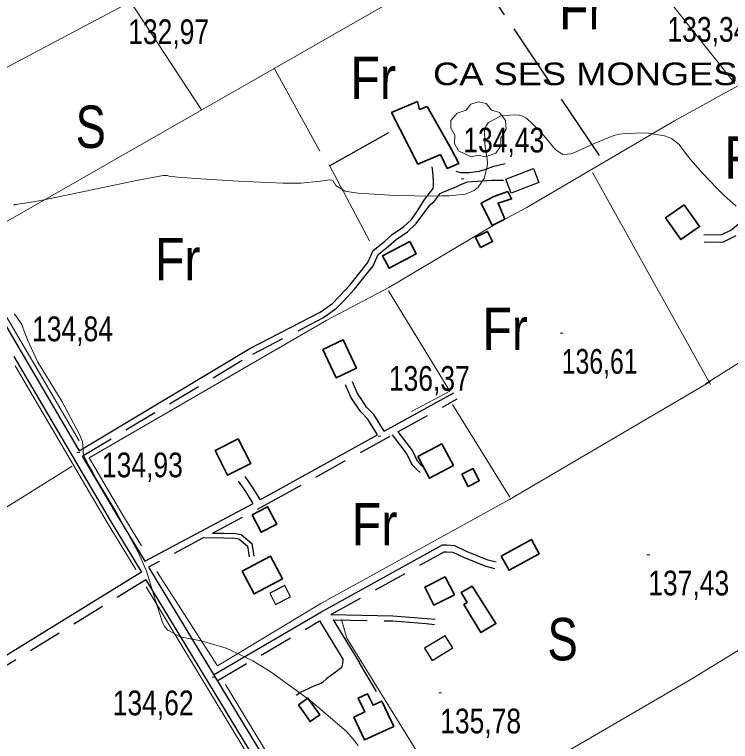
# Model space of a CAD drawing. Extents: x 487425 to 492029, y 4383576 to 4386788.
# Drawn here: x 489592.8 to 489846.1, y 4384922.2 to 4385179.3 of the extents above; entities that cross this region are included whole.
import ezdxf
from ezdxf.enums import TextEntityAlignment as Align

# ---------------------------------------------------------------- set-up
doc = ezdxf.new("R2010")
doc.units = 0
doc.header["$LTSCALE"] = 4
doc.linetypes.add('LONG_DASHED', pattern=[7.5, 6, -1.5])
doc.linetypes.add('MEDIUM_DASHED', pattern=[4.5, 3, -1.5])
for name, color, linetype, lineweight in [('21', 7, 'Continuous', 25), ('25', 7, 'LONG_DASHED', 25), ('29', 7, 'Continuous', 13), ('38', 7, 'Continuous', 25), ('47', 7, 'Continuous', 35), ('51', 7, 'Continuous', 13), ('7', 7, 'Continuous', 13), ('9', 7, 'Continuous', 13)]:
    doc.layers.add(name, color=color, linetype=linetype, lineweight=lineweight)
doc.layers.add('31', color=7, linetype='Continuous')
doc.layers.add('5', color=7, linetype='Continuous')

msp = doc.modelspace()

# ---------------------------------------------------------------- linework, layer by layer
at = {"layer": '21'}
for points in [[(489778.32, 4385119.86), (489768.52, 4385116.11), (489766.63, 4385121.04), (489776.43, 4385124.79)], [(489688.47, 4384977.29), (489683.18, 4384974.65), (489685.17, 4384970.65), (489690.46, 4384973.29)], [(489745.21, 4384959.54), (489737.91, 4384955.11), (489740.53, 4384950.81), (489747.83, 4384955.24)]]:
    msp.add_lwpolyline(points, close=True, dxfattribs=at)
at = {"layer": '25'}
for p, q in [((489752.66, 4385199.06), (489801.25, 4385126.98)), ((489704.3, 4385125.78), (489728.81, 4385139.57))]:
    msp.add_line(p, q, dxfattribs=at)
at = {"layer": '29'}
msp.add_lwpolyline([(489754.4, 4385128.99), (489749.86, 4385131.11), (489748.45, 4385133.65), (489748.55, 4385136.63), (489747.18, 4385139.04), (489747.22, 4385141.79), (489749.38, 4385144.39), (489752.57, 4385145.39), (489754.22, 4385147.58), (489756.79, 4385148.41), (489759.65, 4385147.76), (489761.6, 4385145.49), (489764.41, 4385144.67), (489766.54, 4385141.82), (489766.78, 4385138.69), (489764.9, 4385135.54), (489764.9, 4385132.86), (489763.08, 4385130.25), (489759.46, 4385128.91), (489756.69, 4385129.54)], close=True, dxfattribs=at)
at = {"layer": '38'}
for p, q in [((489723.57, 4385031.89), (489748.22, 4385045.49)), ((489639.32, 4384979.33), (489689.56, 4384896.49)), ((489700.76, 4384964.8), (489708.97, 4384951.29)), ((489705.6, 4384965.24), (489714.9, 4384949.92)), ((489720.9, 4384939.78), (489714.9, 4384949.92))]:
    msp.add_line(p, q, dxfattribs=at)
at = {"layer": '38', "linetype": 'MEDIUM_DASHED'}
for p, q in [((489728.42, 4385031.7), (489749.43, 4385043.3)), ((489659.83, 4384994.28), (489640.17, 4384983.8)), ((489664.52, 4384943.66), (489700.76, 4384964.8))]:
    msp.add_line(p, q, dxfattribs=at)
at = {"layer": '38'}
for points in [[(489405.87, 4385378.35), (489414.38, 4385364.08), (489471.06, 4385268.68), (489565.36, 4385110.65), (489615.64, 4385025.01)], [(489766.39, 4385126.45), (489761.95, 4385125.37), (489759.39, 4385124.42), (489757.2, 4385123.7), (489753.67, 4385123.29), (489750.67, 4385123.25), (489749.03, 4385123.72)], [(489615.64, 4385025.01), (489676.03, 4385061.15), (489700.96, 4385073.97), (489705.26, 4385077.1), (489707.6, 4385079.45), (489711.42, 4385083.56), (489717.76, 4385091.57), (489719.67, 4385095.82), (489723.67, 4385099.03), (489726.44, 4385101.43), (489730.43, 4385104.15), (489733.23, 4385106.81), (489735.41, 4385109.8), (489737.94, 4385113.92), (489739.66, 4385116.12), (489740.87, 4385117.71), (489741.07, 4385118.42), (489741.1, 4385120.51), (489740.77, 4385123.66), (489740.57, 4385125.37)], [(489741.33, 4385113.15), (489743.16, 4385115.61), (489743.46, 4385115.98), (489744.07, 4385116.27), (489749.27, 4385118.46), (489751, 4385119.27), (489753.11, 4385120.07), (489761.67, 4385120.65), (489765.8, 4385120.68)], [(489869.36, 4385119.73), (489856.55, 4385111.57), (489846.56, 4385103.14), (489842.9, 4385101.32), (489836.73, 4385101.19)], [(489592.57, 4385058.29), (489626.63, 4385000.27), (489637.71, 4384982)], [(489723.57, 4385031.89), (489719.92, 4385037.8), (489717.38, 4385040.4), (489715.67, 4385042.96), (489714.11, 4385045.21), (489712.33, 4385049.32)], [(489679.73, 4385007.73), (489682.47, 4385009.19), (489721.27, 4385030.61)], [(489728.42, 4385031.7), (489733.57, 4385024.91), (489735.21, 4385021.45), (489736.62, 4385020.01), (489737.38, 4385019.38)], [(489616.76, 4385023.09), (489629.24, 4385001.83), (489638.87, 4384985.95), (489677.19, 4385006.38)], [(489679.73, 4385007.73), (489676.99, 4385012.15), (489674.39, 4385015.88)], [(489662.87, 4384995.89), (489666.86, 4384995.84), (489671, 4384995.72), (489672.94, 4384995.41), (489676.77, 4384992.13), (489677.48, 4384987.68)], [(489663.25, 4384945.72), (489701.24, 4384967.88), (489744.23, 4384991.69), (489745.7, 4384991.68), (489748.47, 4384991.47), (489752.59, 4384989.52), (489759.92, 4384986.56), (489763.27, 4384985.65)], [(489637.71, 4384982), (489582.92, 4384948.38), (489544.74, 4384923.46), (489507.72, 4384900.4), (489491.99, 4384890.21), (489486.8, 4384886.77), (489484.37, 4384885.41), (489479.48, 4384882.8), (489474.51, 4384879.31), (489472.39, 4384877.41), (489467.24, 4384863.43)], [(489640.17, 4384983.8), (489704.5, 4384877.71), (489716.53, 4384856.91)], [(489704.75, 4384967.06), (489726.7, 4384966.6), (489738.64, 4384965.71), (489741.64, 4384965.38)], [(489708.97, 4384951.29), (489708.86, 4384949.6), (489708.54, 4384948.18), (489703.33, 4384944.48), (489701.81, 4384943), (489701.13, 4384942.63), (489698.94, 4384941.83), (489693.82, 4384939.49), (489692.6, 4384938.38)]]:
    msp.add_lwpolyline(points, dxfattribs=at)
at = {"layer": '38', "linetype": 'MEDIUM_DASHED'}
for points in [[(489942.76, 4385165), (489938.6, 4385160.94), (489931.64, 4385156.64), (489893.93, 4385132.31), (489858.08, 4385109.48), (489847.98, 4385100.96), (489843.53, 4385098.75), (489836.79, 4385098.61)], [(489616.76, 4385023.09), (489677.12, 4385059.2), (489702.13, 4385072.07), (489706.71, 4385075.41), (489709.21, 4385077.91), (489713.11, 4385082.11), (489719.68, 4385090.41), (489721.48, 4385094.42), (489725.1, 4385097.32), (489727.8, 4385099.67), (489731.83, 4385102.41), (489734.91, 4385105.34), (489737.26, 4385108.56), (489739.97, 4385112.04), (489741.33, 4385113.15)], [(489721.27, 4385030.61), (489717.83, 4385036.17), (489715.33, 4385038.73), (489713.49, 4385041.48), (489711.8, 4385043.92), (489709.91, 4385048.28)], [(489662.87, 4384995.89), (489683.67, 4385006.98), (489726.43, 4385030.6)], [(489726.43, 4385030.6), (489731.64, 4385023.73), (489733.34, 4385020.14), (489735.1, 4385018.35), (489736.32, 4385017.34)], [(489677.19, 4385006.38), (489674.59, 4385010.57), (489672.03, 4385014.24)], [(489659.83, 4384994.28), (489666.82, 4384994.19), (489670.85, 4384994.07), (489672.22, 4384993.85), (489675.23, 4384991.27), (489675.84, 4384987.42)], [(489704.75, 4384967.06), (489744.85, 4384989.27), (489745.6, 4384989.26), (489747.84, 4384989.09), (489751.62, 4384987.3), (489759.15, 4384984.26), (489762.63, 4384983.31)], [(489639.32, 4384979.33), (489584.58, 4384945.75), (489546.42, 4384920.83), (489509.4, 4384897.77), (489493.7, 4384887.6), (489488.43, 4384884.11), (489485.87, 4384882.67), (489481.12, 4384880.14), (489476.45, 4384876.87), (489475.05, 4384875.61), (489470.17, 4384862.36)], [(489705.6, 4384965.24), (489726.62, 4384964.8), (489738.48, 4384963.92), (489741.44, 4384963.59)]]:
    msp.add_lwpolyline(points, dxfattribs=at)
at = {"layer": '47'}
for points in [[(489738.86, 4385146.79), (489747.24, 4385131.76), (489749.96, 4385126.63), (489745.89, 4385124.8), (489743.47, 4385129.71), (489735.55, 4385126.35), (489726.23, 4385144.61), (489735.35, 4385148.48), (489736.07, 4385145.7)], [(489767.33, 4385116.68), (489762.43, 4385114.86), (489757.9, 4385112.51), (489761.79, 4385104.67), (489766.24, 4385106.94), (489763.9, 4385112.52), (489768.65, 4385114.04)], [(489829.73, 4385112.02), (489823.14, 4385107.41), (489828.57, 4385099.65), (489835.16, 4385104.26)], [(489757.65, 4385096.84), (489755.88, 4385100.48), (489760.19, 4385102.58), (489761.96, 4385098.94)], [(489732.62, 4385099), (489723, 4385093.87), (489725.31, 4385089.55), (489734.93, 4385094.68)], [(489701.87, 4385060.78), (489706.56, 4385050.8), (489713.8, 4385054.2), (489709.11, 4385064.18)], [(489671.95, 4385029.17), (489676.37, 4385020.43), (489668.21, 4385016.3), (489663.79, 4385025.04)], [(489744.03, 4385027.45), (489735.54, 4385022.91), (489739.62, 4385015.27), (489748.11, 4385019.81)], [(489751.11, 4385016.71), (489753.27, 4385012.4), (489757.24, 4385014.39), (489755.08, 4385018.7)], [(489676.9, 4385002.33), (489682.34, 4385005.18), (489685.57, 4384999), (489680.13, 4384996.15)], [(489765.04, 4384987.75), (489775.7, 4384993.61), (489778.47, 4384988.57), (489767.81, 4384982.71)], [(489673.37, 4384982.34), (489683.4, 4384987.7), (489687.67, 4384979.7), (489677.64, 4384974.34)], [(489745.22, 4384980.39), (489748.42, 4384974.01), (489741.21, 4384970.39), (489738.01, 4384976.77)], [(489754.71, 4384977.06), (489763.11, 4384963.84), (489757.76, 4384960.65), (489751.79, 4384970.64), (489752.92, 4384971.33), (489750.78, 4384974.82)], [(489727.06, 4384927.48), (489722.74, 4384936.46), (489719.65, 4384934.99), (489717.71, 4384939.05), (489714.41, 4384937.48), (489716.72, 4384932.6), (489712.89, 4384930.8), (489716.69, 4384922.71)], [(489693.24, 4384935.15), (489697.39, 4384929.17), (489700.78, 4384931.53), (489696.63, 4384937.51)]]:
    msp.add_lwpolyline(points, close=True, dxfattribs=at)
at = {"layer": '51'}
for p, q in [((489611.69, 4385217.52), (489658.98, 4385145.58)), ((489575.07, 4385097.68), (489765.04, 4385206.13)), ((489700.8, 4385130.94), (489684.68, 4385160.25)), ((489718.44, 4385099.23), (489704.12, 4385126.1)), ((489797.34, 4385123.39), (489839.02, 4385048.42)), ((489747.79, 4385041.36), (489768.05, 4385008.57)), ((489643.21, 4384982.28), (489664.65, 4384948.89)), ((489639.38, 4384976.89), (489687.83, 4384896.99))]:
    msp.add_line(p, q, dxfattribs=at)
for points in [[(489550.2, 4385139.58), (489633.65, 4385183.7), (489711.27, 4385227.74)], [(489792.08, 4385221.73), (489820.66, 4385188.92), (489847.66, 4385154.93)], [(489619.2, 4385022.51), (489703.34, 4385071.12), (489725.23, 4385082.73), (489762.69, 4385105.03), (489773.86, 4385110.91), (489826.28, 4385141.67), (489913.63, 4385190.04)], [(489615.67, 4385028.52), (489566.91, 4385111.57), (489542.2, 4385152.98)], [(489925.77, 4385100.28), (489866.18, 4385066.77), (489837.27, 4385048.63)], [(489725.07, 4385081.53), (489746.79, 4385046.09), (489733.21, 4385038.9)], [(489593.05, 4385055.07), (489625.57, 4384999.64), (489635.67, 4384982.99)], [(489839.03, 4385049.47), (489839.03, 4385049.47), (489767.89, 4385007.74), (489701.15, 4384970.92), (489664.65, 4384948.89)], [(489619.2, 4385022.51), (489630.79, 4385002.75), (489637.72, 4384991.34)], [(489397.04, 4384887.88), (489498.11, 4384948.32), (489554.55, 4384983.01), (489613.25, 4385019.48)], [(489709.41, 4384872.77), (489831.83, 4384944), (489877.76, 4384972.06), (489876.86, 4384971.39), (489897.02, 4384937.03)], [(489748.33, 4384897.23), (489710.39, 4384958.66), (489708.44, 4384965.36)], [(489667.44, 4384942.33), (489706.05, 4384878.63), (489717.23, 4384859.32)]]:
    msp.add_lwpolyline(points, dxfattribs=at)
at = {"layer": '7'}
for p, q in [((489750.82, 4385121.14), (489751.82, 4385121.14)), ((489785.91, 4385066.58), (489786.91, 4385066.58)), ((489721.43, 4385030.1), (489722.43, 4385030.1)), ((489614.91, 4385024.41), (489615.91, 4385024.41)), ((489816.53, 4384988.2), (489817.53, 4384988.2)), ((489662.62, 4384944.87), (489663.62, 4384944.87)), ((489742.9, 4384939.38), (489743.9, 4384939.38))]:
    msp.add_line(p, q, dxfattribs=at)
at = {"layer": '9'}
for points in [[(489592.53, 4385111.9), (489592.96, 4385112.03), (489593.37, 4385112.13), (489594.77, 4385112.3), (489599.47, 4385113.06), (489601.97, 4385113.55), (489604.99, 4385114.14), (489620.22, 4385117.27), (489635.41, 4385120.42), (489638.4, 4385121.02), (489640.87, 4385121.51), (489645.41, 4385122.33), (489646.4, 4385122.34), (489646.63, 4385122.32), (489646.85, 4385122.29), (489647.48, 4385122.09), (489651.54, 4385121.66), (489653.93, 4385121.48), (489656.86, 4385121.27), (489671.99, 4385120.3), (489687.82, 4385119.6), (489691.19, 4385119.57), (489694.12, 4385119.6), (489701.06, 4385120.29), (489704.37, 4385120.75), (489705.02, 4385120.64), (489705.55, 4385120.42), (489706.51, 4385118.77), (489709.83, 4385116.82), (489711.86, 4385116.41), (489714.37, 4385116.05), (489727.45, 4385115.26), (489741.14, 4385115.07), (489744.04, 4385115.1), (489746.55, 4385115.17), (489752.42, 4385115.7), (489755.46, 4385117.03), (489756.19, 4385117.59), (489756.87, 4385118.24), (489758.93, 4385121.28), (489760.02, 4385125.36), (489760.1, 4385126.66), (489760.07, 4385128.03), (489759.15, 4385133.58), (489759.11, 4385138.78), (489759.64, 4385139.92), (489760.4, 4385140.93), (489765.1, 4385143.52), (489770.99, 4385143.75), (489772.5, 4385143.27), (489773.96, 4385142.57), (489778.8, 4385138.07), (489782.76, 4385133.14), (489783.67, 4385132.15), (489784.5, 4385131.33), (489786.83, 4385129.74), (489789.62, 4385130.04), (489790.74, 4385130.4), (489792.01, 4385130.89), (489797.86, 4385133.69), (489804.86, 4385136.45), (489806.85, 4385136.92), (489808.86, 4385137.25), (489816.32, 4385137.39), (489822.73, 4385136.35), (489824.09, 4385135.94), (489825.26, 4385135.47), (489827.95, 4385133.36), (489830.15, 4385130.27), (489831.01, 4385129.2), (489831.98, 4385128.03), (489836.37, 4385123.01), (489841.28, 4385117.81), (489842.58, 4385116.53), (489843.84, 4385115.32), (489848.19, 4385111.5)], [(489595.85, 4385068.23), (489595.35, 4385069.67), (489593.34, 4385072.64), (489592.68, 4385073.46)], [(489696.47, 4384937.4), (489683.62, 4384946.66), (489680.22, 4384948.84), (489677.07, 4384950.73), (489667.71, 4384955.12), (489660.48, 4384957.24), (489658.67, 4384957.7), (489656.94, 4384958.11), (489651.38, 4384959.12), (489647, 4384961.49), (489646, 4384962.75), (489645.11, 4384964.27), (489642.67, 4384971.97), (489639.47, 4384982.44), (489638.09, 4384985.71), (489636.5, 4384989.15), (489628.97, 4385002.92), (489621.75, 4385015.1), (489620.35, 4385017.53), (489619.21, 4385019.54), (489617.27, 4385023.43), (489617.09, 4385024.5), (489617.06, 4385024.75), (489617.04, 4385024.97), (489617.07, 4385025.59), (489616.81, 4385028.21), (489615.79, 4385030.69), (489609.51, 4385042.54), (489601.03, 4385056.28), (489597.38, 4385064.17), (489595.85, 4385068.23)], [(489714.41, 4384920.74), (489712.68, 4384923.03), (489710.42, 4384925.53), (489697.93, 4384936.35), (489696.94, 4384937.06)]]:
    msp.add_lwpolyline(points, dxfattribs=at)

# ---------------------------------------------------------------- texts
at = {"layer": '31'}
for s, width, p in [('Fr', 0.85, (489793.52, 4385174)), ('Fr', 0.85, (489719.72, 4385149.34)), ('S', 0.8, (489619.77, 4385132.08)), ('Fr', 0.85, (489852.05, 4385121.23)), ('Fr', 0.85, (489650.57, 4385085.23)), ('Fr', 0.85, (489766.41, 4385060.58)), ('Fr', 0.85, (489720.2, 4384991.54)), ('S', 0.8, (489786.74, 4384950.85))]:
    msp.add_text(s, height=15, dxfattribs=dict(at, width=width)).set_placement(p, align=Align.CENTER)
at = {"layer": '5', "width": 1.2}
msp.add_text('CA SES MONGES', height=8, dxfattribs=at).set_placement((489740.88, 4385154.29))
at = {"layer": '7'}
for s, width, p in [('132,97', 0.8, (489633.04, 4385168.81)), ('133,34', 0.8, (489823.83, 4385169.64)), ('134,43', 0.8, (489751.61, 4385130.49)), ('134,84', 0.8, (489599.01, 4385063.72)), ('136,61', 0.75, (489786.41, 4385052.21)), ('136,37', 0.8, (489725.25, 4385046.18)), ('134,93', 0.8, (489623.73, 4385015.59)), ('137,43', 0.8, (489817.03, 4384973.83)), ('134,62', 0.8, (489627.54, 4384931.43)), ('135,78', 0.8, (489743.4, 4384925.01))]:
    msp.add_text(s, height=8.75, dxfattribs=dict(at, width=width)).set_placement(p)

doc.saveas('drawing.dxf')
